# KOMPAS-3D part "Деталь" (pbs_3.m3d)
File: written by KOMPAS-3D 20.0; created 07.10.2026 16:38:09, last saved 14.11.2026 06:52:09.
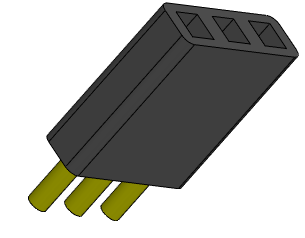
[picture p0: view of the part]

Document properties: Полное имя файла: D:\myProjects\Progect_esp32\box_compas\разъемы\pbs_3.m3d

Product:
- Part/product: Деталь
    Масса: 0.000955835

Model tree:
1. Эскиз:1
2. Элемент выдавливания:1
     Расстояние 1 = 8.5
3. Эскиз:2  (with: Элемент выдавливания:1)
4. Элемент выдавливания:2
     Расстояние 1 = 3
5. Массив по сетке:2  (with: Элемент выдавливания:2, Эскиз:2)  (3 pattern instances)
     Шаг 1 = 2.54; Угол раствора = 90
6. Эскиз:3  (with: Элемент выдавливания:1)
7. Элемент выдавливания:3
     Расстояние 2 = 8
8. Массив по сетке:3  (with: Элемент выдавливания:3, Эскиз:3)  (3 pattern instances)
     Шаг 1 = 2.54; Угол раствора = 90; Геометрический массив = 128
9. Скругление:1  (with: Элемент выдавливания:1)
     Радиус = 0.5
